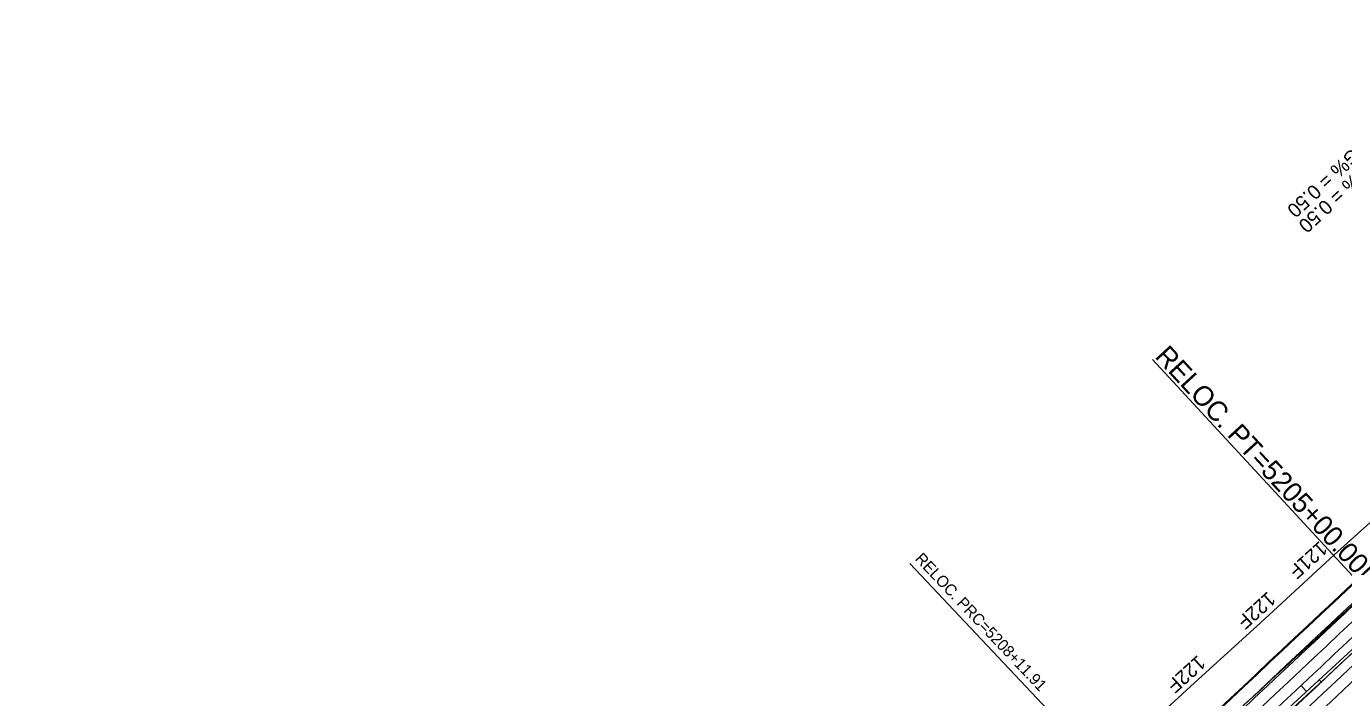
# Model space of a CAD drawing. Extents: x 2160876 to 2175990, y 601436 to 618246.
# Drawn here: x 2168336 to 2169726, y 611423 to 612132 of the extents above; entities that cross this region are included whole.
import ezdxf

# ---------------------------------------------------------------- set-up
doc = ezdxf.new("R2010")
doc.units = 0
for name, color, linetype in [('BNDY-ADJ-TXT', 7, 'Continuous'), ('EX-UTIL-ELEC-TXT', 7, 'Continuous'), ('GN_Transparent 80', 7, 'Continuous'), ('RD_EX_BldgApp_Sign', 7, 'Continuous'), ('RD_EX_BldgApp_Steps', 7, 'Continuous'), ('RD_EX_Fence_Gate', 7, 'Continuous'), ('RD_EX_RW', 7, 'Continuous'), ('RD_HC_Cl', 7, 'Continuous'), ('RD_HC_TX_Sta50', 7, 'Continuous'), ('RD_TX_RoadID', 7, 'Continuous')]:
    doc.layers.add(name, color=color, linetype=linetype)

msp = doc.modelspace()

# ---------------------------------------------------------------- linework, layer by layer
at = {"layer": 'BNDY-ADJ-TXT'}
for centre, start, end in [((2245020.2, 531286.6), 132.719474, 133.338342), ((2095835.3, 692846.5), 312.100607, 312.719474)]:
    msp.add_arc(centre, 110000, start, end, dxfattribs=at)
at = {"layer": 'EX-UTIL-ELEC-TXT'}
for centre, radius, start, end in [((2245020.2, 531286.6), 110041.3, 132.719474, 133.338342), ((2245020.2, 531286.6), 110040.3, 132.719474, 133.338342), ((2245020.2, 531286.6), 110012, 132.719474, 133.338342), ((2245020.2, 531286.6), 110000, 132.719474, 133.338342), ((2245020.2, 531286.6), 109988, 132.719474, 133.338342), ((2095835.3, 692846.5), 109988, 312.100607, 312.719474), ((2095835.3, 692846.5), 110000, 312.100607, 312.719474), ((2095835.3, 692846.5), 110012, 312.100607, 312.719474)]:
    msp.add_arc(centre, radius, start, end, dxfattribs=at)
at = {"layer": 'GN_Transparent 80'}
for radius in [110026.3, 110024]:
    msp.add_arc((2245020.2, 531286.6), radius, 132.719474, 133.338342, dxfattribs=at)
at = {"layer": 'RD_EX_BldgApp_Sign'}
msp.add_arc((2245020.2, 531286.6), 109966, 132.719474, 133.338342, dxfattribs=at)
at = {"layer": 'RD_EX_BldgApp_Steps'}
for p, q in [((2169773.5, 611510.3), (2169524.2, 611780.4)), ((2169773.5, 611510.3), (2165657.1, 607709.2)), ((2169700.1, 611442.5), (2169702.8, 611439.5))]:
    msp.add_line(p, q, dxfattribs=at)
at = {"layer": 'RD_EX_Fence_Gate'}
for p, q in [((2169790, 611641.2), (2169715.7, 611574.4)), ((2169715.7, 611574.4), (2169642.3, 611506.4)), ((2169642.3, 611506.4), (2169568.4, 611439.1)), ((2169568.4, 611439.1), (2169494.5, 611371.4))]:
    msp.add_line(p, q, dxfattribs=at)
at = {"layer": 'RD_EX_RW'}
for p, q in [((2169790, 611641.2), (2169715.7, 611574.4)), ((2169715.7, 611574.4), (2169642.3, 611506.4)), ((2169642.3, 611506.4), (2169568.4, 611439.1)), ((2169568.4, 611439.1), (2169494.5, 611371.4))]:
    msp.add_line(p, q, dxfattribs=at)
for points in [[(2169620.4, 611415.8), (2169638.6, 611432.1), (2169644.4, 611437.6), (2169657.6, 611449.9), (2169668.2, 611459.7), (2169677.3, 611468.3), (2169682.5, 611472.6), (2169695.9, 611484.8), (2169710.6, 611498.5), (2169723.7, 611510.8), (2169736, 611522.3)], [(2169736.7, 611472.1), (2169722.9, 611459.4), (2169707.3, 611444.8), (2169691.4, 611430.2), (2169672.4, 611412.6)]]:
    msp.add_lwpolyline(points, dxfattribs=at)
at = {"layer": 'RD_HC_Cl'}
msp.add_line((2169680.9, 611436.3), (2169686.4, 611430.5), dxfattribs=at)
at = {"layer": 'RD_HC_TX_Sta50'}
msp.add_line((2169268.2, 611565), (2169526.6, 611291.1), dxfattribs=at)
at = {"layer": 'RD_TX_RoadID'}
for centre, radius, start, end in [((2245020.2, 531286.6), 110024, 132.719474, 133.338342), ((2245020.2, 531286.6), 109978, 132.719474, 133.338342), ((2095835.3, 692846.5), 109978, 312.100607, 312.719474), ((2095835.3, 692846.5), 110022, 312.100607, 312.719474)]:
    msp.add_arc(centre, radius, start, end, dxfattribs=at)

# ---------------------------------------------------------------- texts
at = {"layer": 'RD_EX_BldgApp_Steps'}
msp.add_text('RELOC. PT=5205+00.00', height=21, rotation=312.7195, dxfattribs=at).set_placement((2169525.7, 611783))
at = {"layer": 'RD_EX_Fence_Gate'}
for s, p in [('121F', (2169700.3, 611589.6)), ('122F', (2169645.7, 611536.4)), ('122F', (2169571.7, 611469.1))]:
    msp.add_text(s, height=15, rotation=222.2032, dxfattribs=at).set_placement(p)
at = {"layer": 'RD_HC_TX_Sta50'}
for s, height, rotation, p in [('P.T. - LG% = 0.50', 15, 222.7195, (2169783.2, 612049.3)), ('P.C. - LG% = 0.50', 15, 222.7195, (2169796.8, 612034.7)), ('RELOC. PRC=5208+11.91', 12, 313.3383, (2169272.8, 611569.4))]:
    msp.add_text(s, height=height, rotation=rotation, dxfattribs=at).set_placement(p)

doc.saveas('drawing.dxf')
